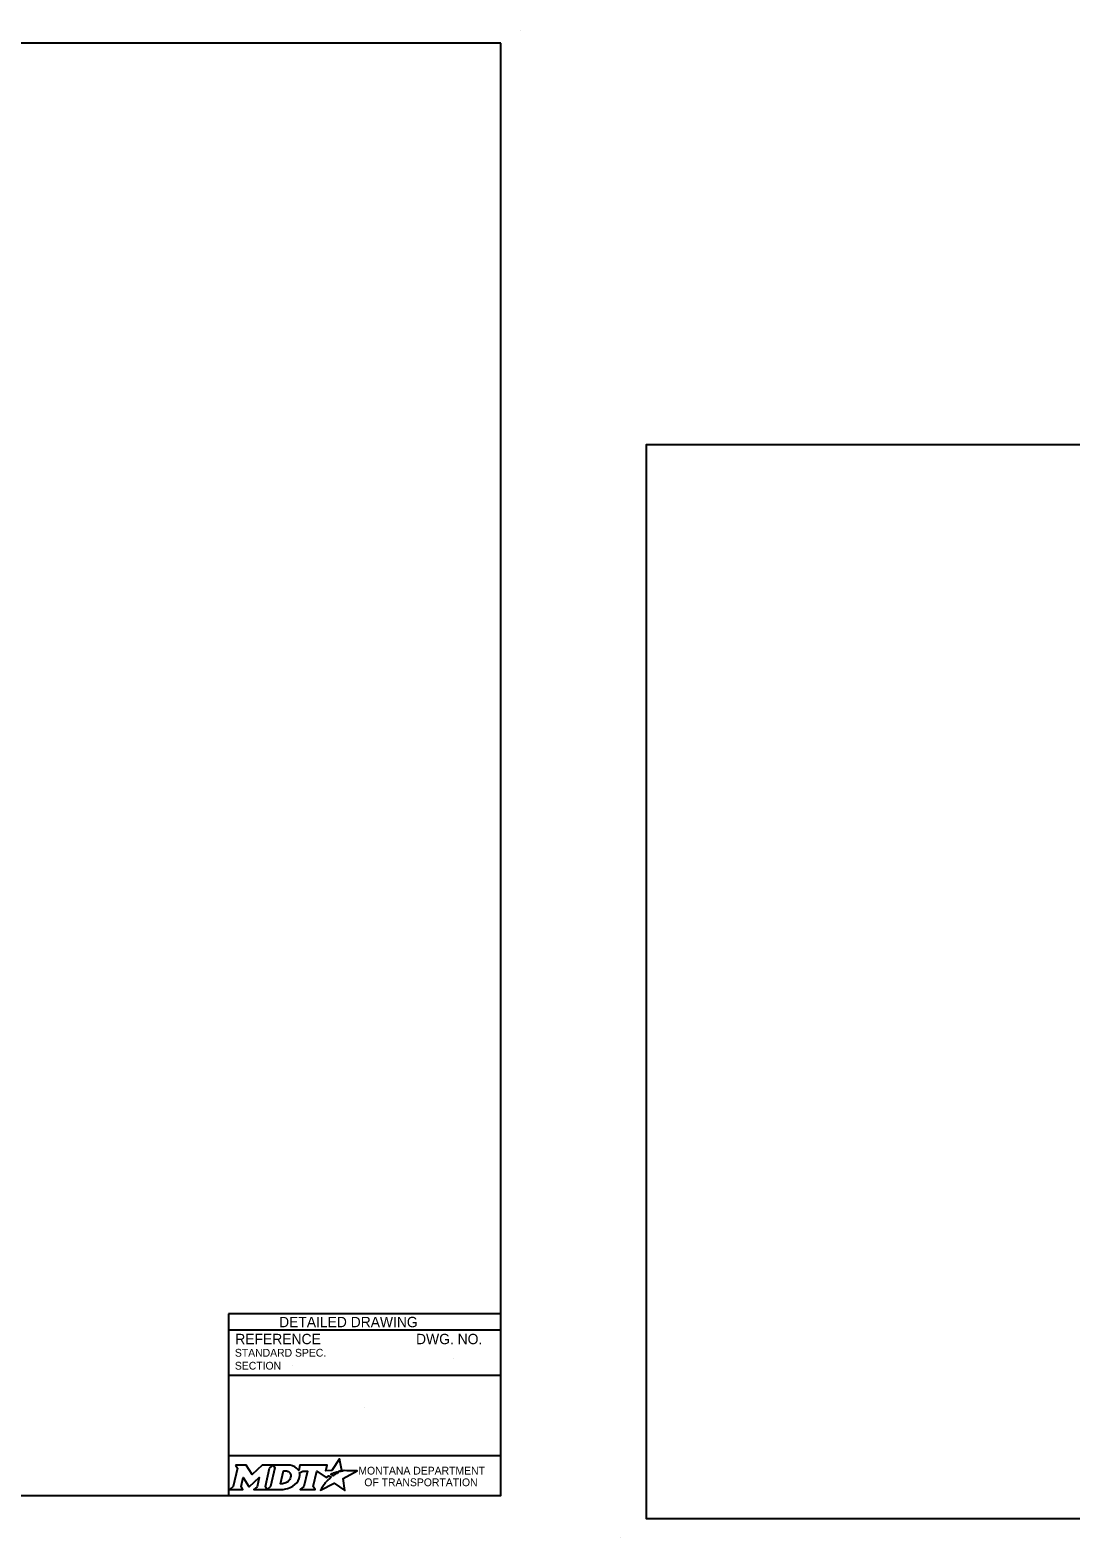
# Model space of a CAD drawing. Extents: x 49991.4 to 50021, y 49987.6 to 50011.4.
# Drawn here: x 50004.99 to 50013.01, y 49999.74 to 50011.36 of the extents above; entities that cross this region are included whole.
import ezdxf

# ---------------------------------------------------------------- set-up
doc = ezdxf.new("R2010")
doc.units = 0
doc.layers.add('Level 1', color=7, linetype='Continuous')
doc.layers.add('Level 2', color=7, linetype='Continuous')

msp = doc.modelspace()

# ---------------------------------------------------------------- linework, layer by layer
at = {"layer": 'Level 1'}
for p, q in [((50008.765, 50011.363), (50008.765, 50011.363)), ((50009.537, 49999.736), (50009.537, 49999.736))]:
    msp.add_line(p, q, dxfattribs=at)
for points in [[(50008.615, 50011.263), (50000.336, 50011.263), (50000.336, 50000.062), (50008.615, 50000.062)], [(50020.938, 50008.165), (50009.737, 50008.165), (50009.737, 49999.886), (50020.938, 49999.886)]]:
    msp.add_lwpolyline(points, close=True, dxfattribs=at)
at = {"layer": 'Level 2'}
for p, q in [((50008.615, 50001.462), (50006.515, 50001.462)), ((50006.515, 50001.462), (50006.515, 50000.062)), ((50008.615, 50001.337), (50006.515, 50001.337)), ((50007.009, 50001.063), (50007.009, 50001.063)), ((50008.251, 50001.122), (50008.251, 50001.122)), ((50008.615, 50000.987), (50006.515, 50000.987)), ((50007.565, 50000.738), (50007.565, 50000.738)), ((50008.615, 50000.369), (50006.515, 50000.369))]:
    msp.add_line(p, q, dxfattribs=at)
for points in [[(50007.377, 50000.245), (50007.367, 50000.25), (50007.378, 50000.253), (50007.39, 50000.255), (50007.373, 50000.345), (50007.313, 50000.254), (50007.266, 50000.253), (50007.276, 50000.297), (50007.067, 50000.297), (50007.057, 50000.255), (50007.051, 50000.263)], [(50006.57, 50000.297), (50006.584, 50000.274), (50006.551, 50000.131), (50006.525, 50000.108), (50006.627, 50000.108), (50006.613, 50000.131), (50006.629, 50000.201), (50006.673, 50000.132), (50006.678, 50000.132), (50006.753, 50000.202), (50006.737, 50000.13), (50006.712, 50000.108), (50006.814, 50000.108), (50006.8, 50000.132), (50006.833, 50000.274)], [(50006.833, 50000.274), (50006.859, 50000.297), (50006.776, 50000.297), (50006.697, 50000.224), (50006.652, 50000.297), (50006.57, 50000.297)], [(50006.972, 50000.297), (50006.859, 50000.297), (50006.873, 50000.275), (50006.839, 50000.131), (50006.814, 50000.108), (50006.925, 50000.108)], [(50006.996, 50000.211), (50006.995, 50000.203), (50006.992, 50000.193), (50006.988, 50000.185), (50006.982, 50000.178), (50006.976, 50000.171), (50006.968, 50000.164), (50006.959, 50000.16), (50006.95, 50000.156), (50006.941, 50000.154), (50006.932, 50000.153), (50006.916, 50000.153), (50006.94, 50000.253), (50006.956, 50000.253), (50006.963, 50000.252), (50006.971, 50000.25), (50006.977, 50000.247), (50006.983, 50000.243), (50006.988, 50000.238), (50006.992, 50000.232), (50006.995, 50000.226), (50006.996, 50000.218), (50006.996, 50000.215), (50006.996, 50000.211)], [(50007.064, 50000.238), (50007.088, 50000.251), (50007.125, 50000.251), (50007.097, 50000.131), (50007.069, 50000.108), (50007.185, 50000.108), (50007.168, 50000.131), (50007.196, 50000.251), (50007.268, 50000.2), (50007.289, 50000.215), (50007.309, 50000.204)], [(50007.253, 50000.148), (50007.237, 50000.124), (50007.233, 50000.116), (50007.227, 50000.107), (50007.225, 50000.103), (50007.33, 50000.156), (50007.414, 50000.101), (50007.401, 50000.194), (50007.508, 50000.252), (50007.458, 50000.253), (50007.428, 50000.253), (50007.407, 50000.254), (50007.401, 50000.252), (50007.396, 50000.251), (50007.387, 50000.249), (50007.377, 50000.245)], [(50007.327, 50000.217), (50007.324, 50000.215), (50007.306, 50000.225), (50007.316, 50000.231), (50007.32, 50000.233), (50007.329, 50000.237), (50007.335, 50000.239), (50007.343, 50000.243), (50007.35, 50000.245), (50007.362, 50000.238), (50007.358, 50000.236), (50007.353, 50000.233), (50007.349, 50000.231), (50007.344, 50000.228), (50007.342, 50000.227), (50007.339, 50000.225), (50007.337, 50000.224), (50007.334, 50000.222), (50007.332, 50000.221), (50007.329, 50000.219), (50007.327, 50000.217)], [(50006.97, 50000.116), (50006.979, 50000.118), (50006.992, 50000.124), (50007.012, 50000.135)], [(50007.267, 50000.164), (50007.267, 50000.164)]]:
    msp.add_lwpolyline(points, dxfattribs=at)
for centre, radius, start, end in [((50006.995, 50000.219), 0.0709, 339.5329, 15.8582), ((50006.951, 50000.236), 0.118, 300.9103, 339.1383)]:
    msp.add_arc(centre, radius, start, end, dxfattribs=at)
for centre, major_axis, ratio, start_param, end_param in [((50006.97, 50000.25), (0.0834, -0.0037), 0.568097, 0.61298, 1.570796), ((50007.026, 50000.257), (0.0361, -0.0295), 0.469099, 1.225588, 1.570796), ((50006.925, 50000.257), (0, 0.148), 0.987302, 3.139398, 3.456847), ((50007.26, 50000.156), (-0.00694, -0.00806), 0.008222, 0, 3.137361), ((50007.276, 50000.174), (-0.0098, -0.0102), 0.016458, 3.141593, 6.279097), ((50007.297, 50000.194), (-0.0112, -0.0097), 0.021651, 3.157348, 6.283185)]:
    msp.add_ellipse(centre, major_axis=major_axis, ratio=ratio, start_param=start_param, end_param=end_param, dxfattribs=at)

# ---------------------------------------------------------------- texts
for s, height, p in [('DETAILED DRAWING', 0.0799, (50006.906, 50001.36)), ('REFERENCE', 0.08, (50006.568, 50001.229)), ('DWG. NO.', 0.08, (50007.962, 50001.229)), ('STANDARD SPEC.', 0.06, (50006.565, 50001.133)), ('SECTION', 0.06, (50006.565, 50001.033))]:
    msp.add_text(s, height=height, dxfattribs=at).set_placement(p)
for s, p in [('MONTANA DEPARTMENT', (50007.517, 50000.224)), ('OF TRANSPORTATION', (50007.563, 50000.134))]:
    msp.add_text(s, height=0.06, rotation=360, dxfattribs=at).set_placement(p)

doc.saveas('drawing.dxf')
